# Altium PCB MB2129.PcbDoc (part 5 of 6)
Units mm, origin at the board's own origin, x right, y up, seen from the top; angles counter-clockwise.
Board outline 70 x 133.34 mm, 6 copper layers (Top Layer, Signal Layer 1, Signal Layer 2, Signal Layer 3, Signal Layer 4, Bottom Layer), stack 1.57 mm thick; 377 components, 289 nets, 1482 pads, 1373 vias.
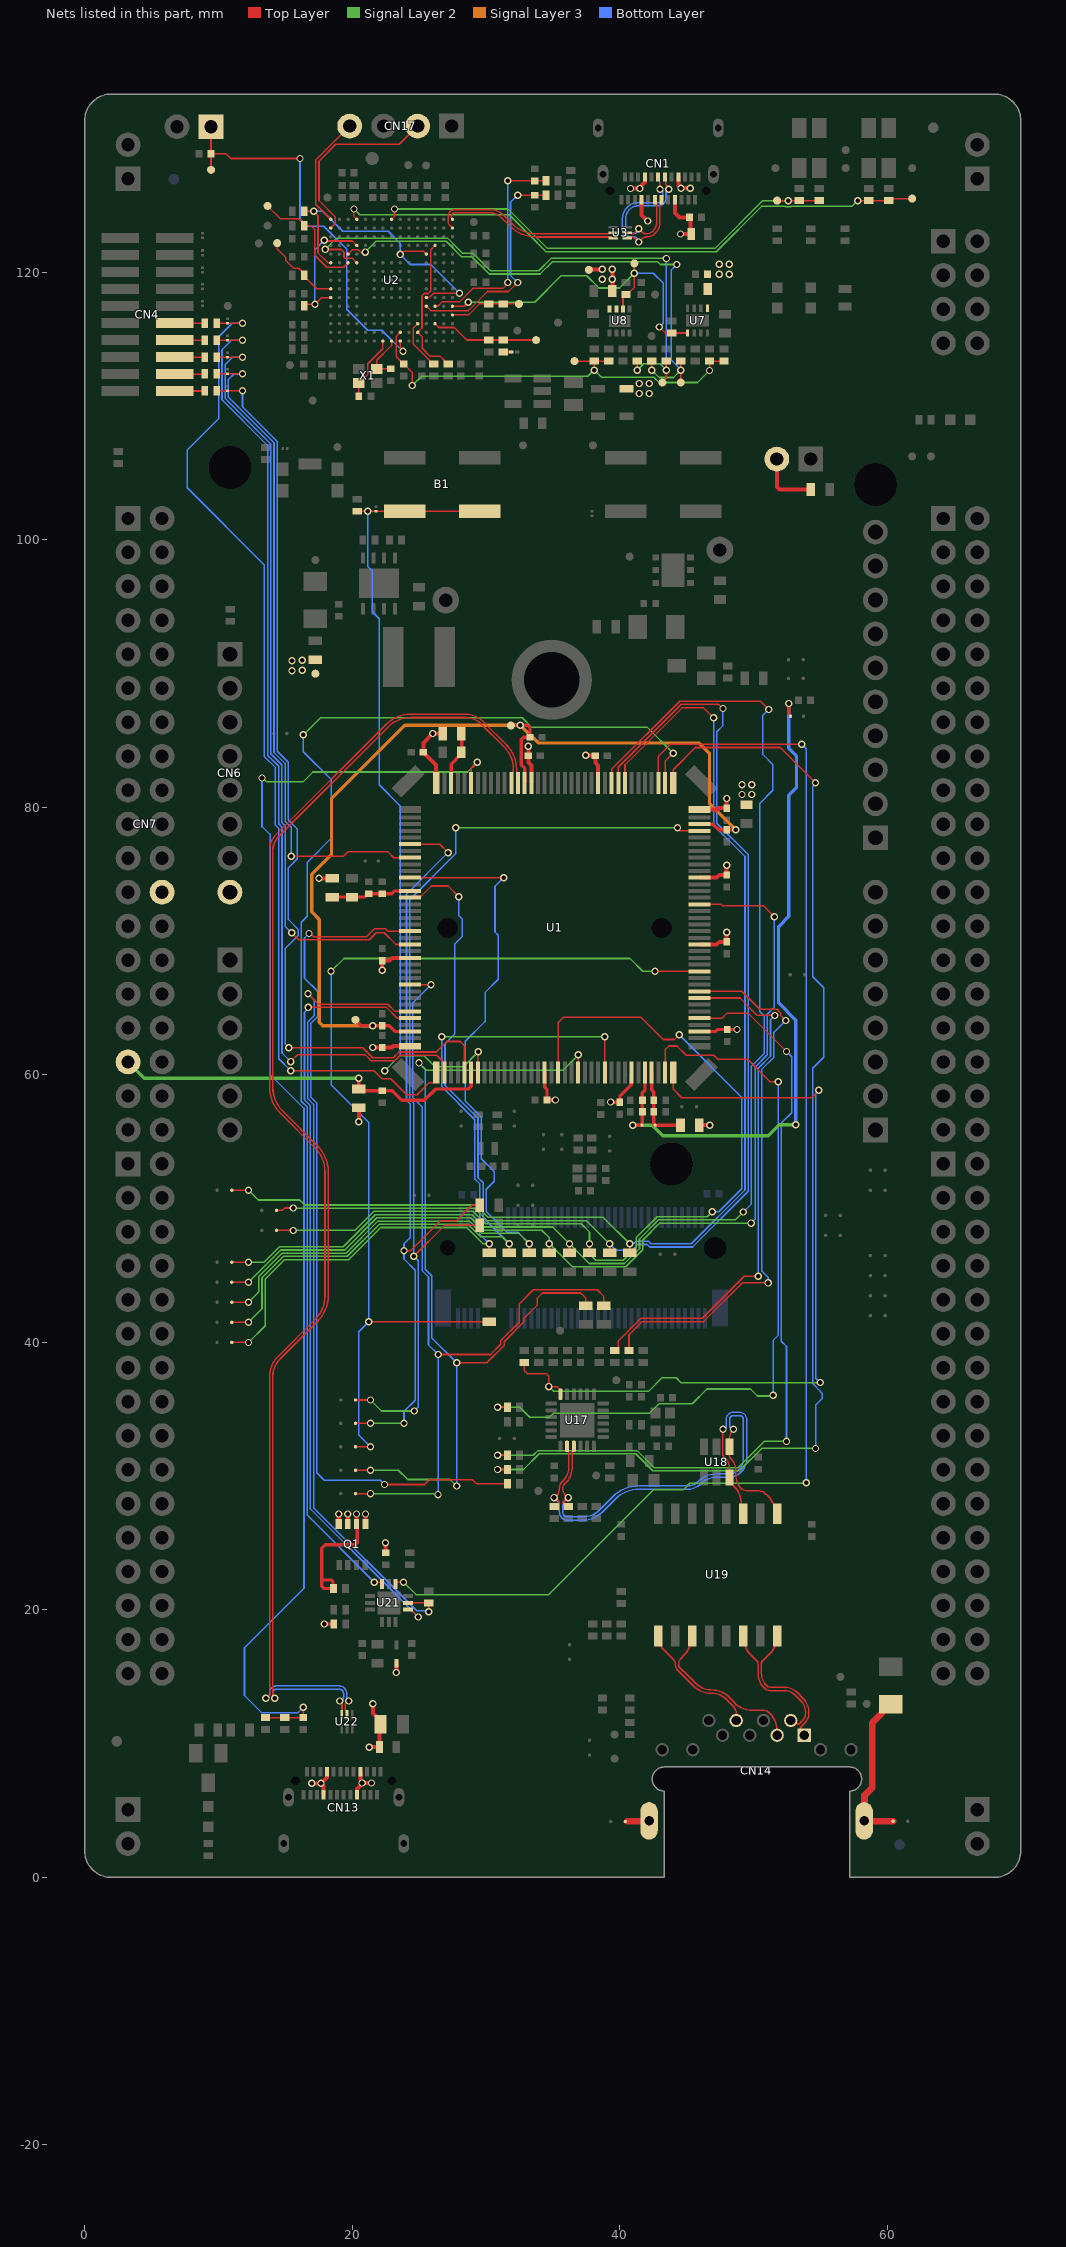
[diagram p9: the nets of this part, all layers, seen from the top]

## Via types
v1: diameter 0.55, hole 0.35, Top Layer to Bottom Layer, tented both sides, 1373 vias

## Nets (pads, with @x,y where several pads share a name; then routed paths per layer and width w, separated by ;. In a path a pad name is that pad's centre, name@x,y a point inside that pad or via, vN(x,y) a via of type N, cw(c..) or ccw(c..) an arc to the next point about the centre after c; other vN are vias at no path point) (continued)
RMII.MDIO: R69.1 U1.36 U17.12 | length 60.4
  Top Layer w0.12: R69.1@32.875,38.5 32.875,37.9 33.104,37.671 34.529,37.671 34.71,37.49 v1(34.71,36.7) 35.304,36.7 35.575,36.429 U17.12@35.575,36.125 ; U1.36@44,60.175 44,58.956 44.651,58.305 46.525,58.305 46.53,58.3 54.35,58.3 v1(54.9,58.85)
  Signal Layer 2 w0.12: v1(34.71,36.7) 35.07,36.34 42.155,36.34 43.165,37.35 44.225,37.35 44.575,37 v1(55,37)
  Bottom Layer w0.12: v1(54.9,58.85) 54.9,58.805 54.67,58.575 54.67,37.33 v1(55,37)
RMII.REF_CLK: R77.1 U1.35 | length 57.8
  Top Layer w0.12: v1(30.875,35.15) R77.1@31.625,35.15 ; U1.35@43.4,60.175 43.4,61.875 43.693,62.168 44.288,62.168 44.976,61.48 47.041,61.48 47.351,61.17 49.58,61.17 51.25,59.5 v1(51.85,59.5)
  Signal Layer 2 w0.12: v1(30.875,35.15) 32.525,35.15 33.275,34.4 34.75,34.4 35.045,34.695 42.222,34.695 42.942,35.415 45.429,35.415 46.534,36.52 49.78,36.52 50.305,35.995 51.42,35.995 v1(51.475,36.05)
  Bottom Layer w0.12: v1(51.475,36.05) 51.475,40.15 51.85,40.525 v1(51.85,59.5)
RMII.RXD0: R74.1 U1.44 | length 39.5
  Top Layer w0.12: R74.1@39.625,39.4 39.705,39.4 39.9,39.595 39.9,40.106 41.594,41.8 46.175,41.8 49.325,44.95 v1(50.375,44.95) ; U1.44@45.975,65.75 49,65.75 50.3,64.45 v1(51.6,64.45)
  Bottom Layer w0.12: v1(50.375,44.95) 50.375,60.502 51.284,61.411 51.284,64.134 v1(51.6,64.45)
RMII.RXD1: R75.1 U1.45 | length 41.2
  Top Layer w0.12: R75.1@40.7,39.4 40.7,40.567 41.693,41.56 46.274,41.56 49.164,44.45 v1(51.1,44.45) ; U1.45@45.975,66.25 49.125,66.25 50.47,64.905 51.412,64.905 51.788,64.905 52.055,64.638 52.055,64.445 v1(52.425,64.075)
  Bottom Layer w0.12: v1@51.1,44.454 51.1,44.868 50.615,45.353 50.615,60.402 51.524,61.311 51.524,63.174 v1(52.425,64.075)
RMII.TX_EN: R80.1 U1.41 | length 61.5
  Top Layer w0.12: v1(30.875,31.575) R80.1@31.625,31.575 ; U1.41@45.975,64.25 47.65,64.25 48.025,64.625 49.6,64.625 v1(52.475,61.75)
  Signal Layer 2 w0.12: v1(30.875,31.575) 33.55,31.575 33.89,31.915 41.3,31.915 42.575,30.64 48.855,30.64 50.815,32.6 v1(52.475,32.6)
  Bottom Layer w0.12: v1(52.475,32.6) 52.475,39.696 52.09,40.081 52.09,56.402 52.87,57.182 52.87,61.355 v1(52.475,61.75)
RMII.TXD0: R82.1 U1.73 | length 90.7
  Top Layer w0.12: v1(30.875,30.5) R82.1@31.625,30.5 ; U1.73@44,81.825 44,82.827 45.658,84.485 52.015,84.485 v1(54.65,81.85)
  Signal Layer 2 w0.12: v1(30.875,30.5) 32.814,30.5 33.989,31.675 41.2,31.675 42.475,30.4 48.955,30.4 50.655,32.1 54.625,32.1 v1(54.65,32.075)
  Bottom Layer w0.12: v1(54.65,32.075) 54.65,35.307 55.155,35.812 55.155,36.188 54.99,36.353 54.99,36.367 54.43,36.927 54.43,60.505 55.255,61.33 55.255,66.527 54.43,67.352 54.43,81.565 54.65,81.785 v1(54.65,81.85)
RMII.TXD1: R83.1 U1.127 | length 64.1
  Top Layer w0.12: v1(16.775,70.575) 16.891,70.575 17.126,70.34 21.068,70.34 21.645,70.917 22.521,70.917 22.688,70.75 U1.127@24.325,70.75 ; v1(22.425,29.375) 25.425,29.375 25.775,29.725 29,29.725 29.3,29.425 R83.1@31.625,29.425
  Bottom Layer w0.12: v1(16.775,70.575) 16.44,70.24 16.44,67.235 17.42,66.255 17.42,64.365 16.92,63.865 16.92,58.336 17.36,57.896 17.36,30.264 17.924,29.7 22.1,29.7 v1(22.425,29.375)
RX_N: CN14.6 U19.9 | length 9.3
  Top Layer w0.1: U19.9@42.88,18.05 ccw(c44.401,18.05) 43.325,16.975 43.998,16.302 cw(c43.571,15.875) 44.175,15.875 ccw(c44.718,15.875) 44.334,15.491 45.502,14.323 ccw(c46.825,15.646) 46.825,13.775 cw(c46.825,12.085) 48.02,13.28 48.475,12.825 cw(c47.896,12.246) 48.715,12.246 CN14.6@48.715,11.73
RX_P: CN14.3 U19.11 | length 12.4
  Top Layer w0.1: U19.11@45.42,18.05 cw(c43.416,18.05) 44.833,16.633 44.6,16.4 ccw(c45.022,15.978) 44.425,15.978 44.425,15.875 ccw(c44.718,15.875) 44.511,15.667 45.077,15.102 45.679,14.5 ccw(c46.825,15.646) 46.825,14.025 cw(c46.825,12.085) 48.193,13.46 48.564,13.089 48.65,13.003 cw(c48.58,12.932) 48.655,12.999 48.727,12.918 ccw(c49.938,14.463) 49.938,12.5 50.682,12.5 cw(c50.682,11.732) 51.225,12.275 cw(c49.897,10.947) 51.775,10.947 CN14.3@51.775,10.63
SHGND: C100.1 CN14.SH1 CN14.SH2 SB43.1 SB44.1 | length 13.4
  Top Layer w0.5: 40.58,4.2 CN14.SH2@42.235,4.2 ; C100.1@60.275,12.95 58.9,11.575 58.9,6.719 58.315,6.134 58.315,4.2 SB43.1@60.45,4.2
STLK_LED: R11.1 R12.2 TP10.1 U2.D15 | length 45.6
  Top Layer w0.12: v1(20.135,124.75) 20.135,124.19 U2.D15@20.35,123.975 ; v1(57.8,125.375) R11.1@58.625,125.375 R12.2@60.125,125.375 60.275,125.525 TP10.1@61.875,125.525
  Signal Layer 2 w0.12: v1(20.135,124.75) 20.57,124.315 31.746,124.315 33.236,122.824 34.501,121.56 47.224,121.56 50.604,124.94 52.392,124.94 52.412,124.92 52.788,124.92 52.808,124.94 57.365,124.94 v1(57.8,125.375)
STLK_NRST: C1.2 JP3.1 TP8.1 U2.J1 | length 29.8
  Top Layer w0.12: JP3.1@9.445,130.9 9.445,128.88 C1.2@9.45,128.875 ; TP8.1@9.45,127.675 C1.2@9.45,128.875 ; v1(16.1,128.525) 10.925,128.525 10.575,128.875 C1.2@9.45,128.875 ; U2.J1@23.6,114.875 23.6,114.385 23.8,114.185 v1(23.8,114.1)
  Bottom Layer w0.12: v1(16.1,128.525) 16.1,124.034 16.671,123.463 17.887,123.463 19.597,121.753 19.597,117.244 21.166,115.675 22.225,115.675 v1(23.8,114.1)
STLK_OSC_IN: C35.2 U2.G1 X1.1 | length 4.9
  Top Layer w0.12: C35.2@20.5,110.75 X1.1@20.5,111.75 20.55,111.75 21.175,112.375 21.175,113.175 22.3,114.3 U2.G1@22.3,114.875
STLK_OSC_OUT: C33.1 U2.H1 X1.3 | length 3.7
  Top Layer w0.12: X1.3@21.6,112.8 21.85,113.05 21.85,113.44 22.95,114.54 U2.H1@22.95,114.875 ; X1.3@21.85,112.8 C33.1@22.875,112.8
STLK_SWCLK: CN17.2 U2.A14 | length 14.1
  Top Layer w0.12: U2.A14@18.4,123.325 18.725,123.65 18.725,124.175 17.525,125.375 17.525,128.321 18.784,129.58 23.525,129.58 CN17.2@24.895,130.95
STLK_SWDIO: CN17.4 U2.A15 | length 8.5
  Top Layer w0.12: U2.A15@18.4,123.975 17.275,125.1 17.275,128.41 CN17.4@19.815,130.95
STLK_UCPD_CC1_C: C10.1 R13.1 U2.M5 | length 16.9
  Top Layer w0.12: U2.M5@25.55,117.475 25.875,117.15 28.7,117.15 30.125,118.575 31.7,118.575 v1(32.375,119.25) ; v1(32.375,125.775) C10.1@33.65,125.775 R13.1@34.5,125.775
  Bottom Layer w0.12: v1(32.375,119.25) 31.845,119.78 31.845,125.245 v1(32.375,125.775)
STLK_UCPD_CC2_C: C2.1 R6.1 U2.N5 | length 16.7
  Top Layer w0.12: U2.N5@26.2,117.475 26.4,117.475 26.725,117.8 28.025,117.8 29.06,118.835 31.312,118.835 31.625,119.148 v1(31.625,119.25) ; v1(31.625,126.85) C2.1@33.65,126.85 R6.1@34.5,126.85
  Bottom Layer w0.12: v1(31.625,119.25) v1(31.625,126.85)
STLK_USB_CN_N: CN1.A7 CN1.B7 U3.2 | length 12.6
  Top Layer w0.12: U3.2@40.575,122.975 40.768,122.975 cw(c40.768,122.838) 40.865,122.935 ccw(c40.962,123.032) 40.962,122.895 ccw(c40.962,123.096) 41.104,122.954 v1(41.425,123.275) 41.685,123.015 ccw(c41.975,123.305) 41.975,122.895 42.005,122.895 ccw(c42.005,123.595) 42.5,123.1 ccw(c41.86,123.74) 42.765,123.74 42.765,125.018 ccw(c42.543,125.018) 42.7,125.175 cw(c42.857,125.332) 42.635,125.332 CN1.A7@42.635,125.44 ; CN1.B7@43.385,127.14 43.46,127.065 43.46,126.566 43.685,126.341 v1(43.685,126.225)
  Bottom Layer w0.12: v1(41.425,123.275) cw(c41.075,123.275) 41.075,122.925 40.75,122.925 cw(c40.75,123.225) 40.45,123.225 40.45,124.025 cw(c41.41,124.025) 41.41,124.985 42.88,124.985 ccw(c42.88,125.575) 43.47,125.575 43.47,126.01 cw(c43.685,126.01) v1(43.685,126.225)
STLK_USB_CN_P: CN1.A6 CN1.B6 U3.1 | length 13.3
  Top Layer w0.12: U3.1@40.575,122.575 40.768,122.575 ccw(c40.768,122.712) 40.865,122.615 cw(c40.962,122.518) 40.962,122.655 cw(c40.962,122.454) 41.104,122.596 v1(41.425,122.275) 41.685,122.535 cw(c41.975,122.245) 41.975,122.655 42.005,122.655 ccw(c42.005,123.595) 42.67,122.93 ccw(c41.86,123.74) 43.005,123.74 43.005,125.018 cw(c43.227,125.018) 43.07,125.175 ccw(c42.913,125.332) 43.135,125.332 CN1.A6@43.135,125.44 ; CN1.B6@42.885,127.14 42.975,127.05 42.975,126.81 43.015,126.77 v1(43.015,126.225)
  Bottom Layer w0.12: v1(41.425,122.275) ccw(c41.015,122.275) 41.015,122.685 40.75,122.685 cw(c40.75,123.225) 40.21,123.225 40.21,124.025 cw(c41.41,124.025) 41.41,125.225 42.88,125.225 ccw(c42.88,125.575) 43.23,125.575 43.23,126.01 ccw(c43.015,126.01) v1(43.015,126.225)
STLK_USB_N: U2.R14 U3.5 | length 14.2
  Top Layer w0.12: U2.R14@27.5,123.325 27.334,123.491 cw(c27.718,123.875) 27.175,123.875 27.175,124.188 cw(c27.687,124.188) 27.325,124.55 cw(c27.687,124.188) 27.687,124.7 30.306,124.7 cw(c30.306,123.231) 31.345,124.27 31.975,123.639 ccw(c33.772,125.435) 33.772,122.895 39.138,122.895 ccw(c39.138,123.032) 39.235,122.935 cw(c39.332,122.838) 39.332,122.975 U3.5@39.525,122.975
STLK_USB_P: U2.R15 U3.6 | length 13.1
  Top Layer w0.12: U2.R15@27.5,123.975 cw(c27.741,124.216) 27.423,124.094 cw(c27.535,124.136) 27.415,124.136 27.415,124.188 cw(c27.687,124.188) 27.427,124.267 cw(c27.687,124.188) 27.495,124.38 cw(c27.687,124.188) 27.687,124.46 30.306,124.46 cw(c30.306,123.231) 31.175,124.1 31.806,123.469 ccw(c33.772,125.435) 33.772,122.655 39.138,122.655 cw(c39.138,122.518) 39.235,122.615 ccw(c39.332,122.712) 39.332,122.575 U3.6@39.525,122.575
STLK_VCP_RX: R16.1 TP12.1 U2.C10 | length 9.2
  Top Layer w0.12: TP12.1@13.675,124.975 14.64,124.01 16.006,124.01 16.421,123.595 R16.1@16.421,123.5 16.925,123.5 17.21,123.215 17.21,121.29 18.1,120.4 19.375,120.4 U2.C10@19.7,120.725
STLK_VCP_TX: R20.1 TP16.1 U2.A7 | length 5.9
  Top Layer w0.12: TP16.1@14.4,122.2 14.4,121.758 15.05,121.108 15.05,120.875 15.615,120.31 16.01,120.31 16.425,119.895 16.425,119.705 17.355,118.775 U2.A7@18.4,118.775
T_JTDI: R44.1 U2.L3 | length 3.8
  Top Layer w0.12: U2.L3@24.9,116.175 24.575,115.85 24.575,114.65 25.81,113.415 25.81,113.345 26.005,113.15 R44.1@26.1,113.15
T_PWR_EN: R21.2 R25.2 TP21.1 U2.R5 U7.5 U8.2 | length 27.4
  Top Layer w0.12: U2.R5@27.5,117.475 28.375,117.475 v1(28.675,117.775) ; U8.2@40.25,117.275 40.25,118.155 40.445,118.35 R21.2@40.475,118.35 40.57,118.35 41.1,118.88 v1(41.1,119.95) TP21.1@41.1,120.675 ; v1(42.975,115.925) 43.425,115.475 R25.2@43.9,115.475 U7.5@45.075,115.475
  Signal Layer 2 w0.12: v1(28.675,117.775) 33.65,117.775 35.625,119.75 37.549,119.75 38.458,118.841 39.991,118.841 v1(41.1,119.95)
  Bottom Layer w0.12: v1(41.1,119.95) 42.525,119.95 43.26,119.215 43.26,116.21 v1(42.975,115.925)
T_PWR_EXT: R23.1 R24.1 TP24.1 U2.R4 | length 5.3
  Top Layer w0.12: U2.R4@27.5,116.825 28.7,116.825 29.525,117.65 R23.1@30.225,117.65 R24.1@31.3,117.65 TP24.1@32.475,117.65
T_PWR_INT: C28.1 R33.2 R40.2 R41.2 R42.2 TP30.1 U2.J2 | length 33.1
  Top Layer w0.12: U2.J2@23.6,115.525 23.29,115.215 23.29,113.71 23.63,113.37 23.63,113.345 23.825,113.15 C28.1@23.85,113.15 23.875,113.15 24.5,112.525 v1(24.5,111.55) ; TP30.1@36.625,113.375 R33.2@38.1,113.375 ; v1(38.1,112.7) R33.2@38.1,113.375 ; R42.2@39.175,113.375 R33.2@38.1,113.375 ; v1(46.725,112.675) R40.2@46.725,113.375 R41.2@47.8,113.375
  Signal Layer 2 w0.12: v1(24.5,111.55) 25.2,112.25 37.625,112.25 38.1,112.725 38.65,112.175 42.55,112.175 42.95,111.775 45.825,111.775 v1(46.725,112.675)
T_PWR_LED: R9.2 R10.2 TP11.1 U2.H15 | length 36.2
  Top Layer w0.12: U2.H15@22.95,123.975 23.165,124.19 v1(23.165,124.75) ; TP11.1@51.775,125.375 v1(52.6,125.375) R9.2@53.425,125.375 R10.2@54.925,125.375
  Signal Layer 2 w0.12: v1(23.165,124.75) 31.65,124.75 34.6,121.8 47.125,121.8 50.7,125.375 v1(52.6,125.375)
T_PWR_SEL1: R35.2 R37.2 TP32.1 U2.D10 | length 43.8
  Top Layer w0.12: v1(17.98,121.725) 17.985,121.72 19.18,121.72 19.395,121.505 19.395,121.13 19.475,121.05 20.025,121.05 U2.D10@20.35,120.725 ; v1(41.325,112.7) R35.2@41.325,113.375 ; TP32.1@42.95,111.775 TP32.1@43.075,111.9 ; TP32.1@43.2,111.775 43.49,112.065 43.49,112.69 v1(43.5,112.7) R37.2@43.5,113.375
  Signal Layer 2 w0.12: v1(17.98,121.725) 18.828,122.573 27.127,122.573 28.275,121.425 29.05,121.425 30.35,120.125 33.95,120.125 34.875,121.05 v1(43.5,121.05) ; v1(41.325,112.7) 41.805,113.18 43.02,113.18 v1(43.5,112.7)
  Bottom Layer w0.12: v1(43.5,112.7) v1(43.5,121.05)
T_PWR_SEL2: R36.2 R38.2 TP33.1 U2.C11 | length 39.9
  Top Layer w0.12: U2.C11@19.7,121.375 20.025,121.7 20.456,121.7 20.631,121.525 v1(20.975,121.525) ; v1(42.4,112.7) R36.2@42.4,113.375 ; TP33.1@44.575,111.775 v1(44.575,112.7) R38.2@44.575,113.375
  Signal Layer 2 w0.12: v1(20.975,121.525) 21.783,122.333 27.028,122.333 28.176,121.185 28.951,121.185 30.251,119.885 34.049,119.885 34.974,120.81 42.84,120.81 43.055,120.595 44.27,120.595 v1(44.275,120.6) ; v1(42.4,112.7) 42.95,112.15 44.025,112.15 v1(44.575,112.7)
  Bottom Layer w0.12: v1(44.275,120.6) 43.85,120.175 43.85,113.468 44.575,112.743 v1(44.575,112.7)
T_SWCLK: R15.1 U2.A10 U2.M6 U2.M11 | length 23.9
  Top Layer w0.12: R15.1@16.421,124.575 v1@17.141,124.575 ; v1(17.141,124.57) 17.141,124.545 17.45,124.236 17.45,121.463 18.188,120.725 U2.A10@18.4,120.725 ; v1(23.6,121.35) 23.635,121.35 23.885,121.6 25.325,121.6 U2.M11@25.55,121.375 ; U2.M6@25.55,118.125 25.769,118.125 26.094,118.45 v1(28.025,118.45)
  Bottom Layer w0.12: v1(17.141,124.57) 17.805,124.57 19.3,123.075 22.7,123.075 23.6,122.175 v1(23.6,121.35) 24.35,120.6 25.875,120.6 v1(28.025,118.45)
T_SWDIO: R45.1 U2.L2 U2.N12 | length 11
  Top Layer w0.12: U2.N12@26.2,122.025 25.875,121.7 25.875,118.625 25.68,118.43 25.386,118.43 25.225,118.269 25.225,115.85 U2.L2@24.9,115.525 25.245,115.18 25.245,114.326 25.846,113.725 26.6,113.725 26.885,113.44 26.885,113.345 27.08,113.15 R45.1@27.175,113.15
T_SWO: R22.1 U2.A6 U2.D12 | length 9.9
  Top Layer w0.12: R22.1@16.425,117.525 16.53,117.63 v1(17.22,117.63) ; v1@17.225,117.625 17.725,118.125 U2.A6@18.4,118.125 ; v1(17.925,122.4) 17.97,122.355 18.529,122.355 20.02,122.355 U2.D12@20.35,122.025
  Bottom Layer w0.12: v1(17.22,117.63) 17.22,121.695 v1(17.925,122.4)
T_VCC: LNK1.2 R31.2 | length 0.6
  Top Layer w0.2: R31.2@31.3,114.05 LNK1.2@31.9,114.05
T_VCC_AIN: R30.1 R31.1 TP29.1 U2.N3 | length 8.1
  Top Layer w0.12: U2.N3@26.2,116.175 26.485,115.89 27.637,115.89 28.577,114.95 R30.1@30.225,114.95 R31.1@31.3,114.95 TP29.1@33.75,114.95
TD_N: R84.1 U17.20 U18.3 U19.3 | length 35.5
  Top Layer w0.1: R84.1@35.1,27.725 35.257,27.882 cw(c35.373,27.765) 35.373,27.93 35.4,27.93 ccw(c35.4,28.03) 35.471,27.959 ccw(c35.4,28.03) 35.5,28.03 ccw(c35.4,28.03) 35.471,28.101 35.222,28.349 ccw(c35.1,28.228) v1(35.1,28.4) ccw(c35.1,28.578) 35.226,28.452 ccw(c34.565,29.113) 35.5,29.113 cw(c36.161,29.113) 35.694,29.581 35.79,29.677 ccw(c34.799,30.668) 36.2,30.668 36.2,30.705 ; U17.20@36.075,32.225 36.075,32.025 ccw(c36.288,32.025) 36.137,31.874 cw(c35.987,31.723) 36.2,31.723 36.2,30.705 ; 36.2,30.601 36.2,30.705 ; v1@47.724,33.516 47.724,31.651 ccw(c48.22,31.651) 47.768,31.447 47.994,31.222 cw(c47.495,30.723) 48.2,30.723 U18.3@48.2,29.9 ccw(c48.924,29.9) 48.412,29.388 48.62,29.18 cw(c47.509,28.069) 49.08,28.069 U19.3@49.08,27.2
  Bottom Layer w0.1: v1(35.1,28.4) 35.306,28.194 cw(c34.836,27.725) 35.5,27.725 35.5,27.325 ccw(c36.125,27.325) 36.125,26.7 37.2,26.7 ccw(c37.2,28.821) 38.7,27.321 39.66,28.281 cw(c41.456,26.485) 41.456,29.025 45.136,29.025 ccw(c45.136,30.214) 45.977,29.373 45.983,29.38 cw(c47.3,28.063) 47.3,29.925 48.14,29.925 ccw(c48.14,31.285) 49.102,30.323 ccw(c48.14,31.285) 49.5,31.285 49.5,34.25 ccw(c48.975,34.25) 48.975,34.775 48.475,34.775 ccw(c48.475,34.273) 47.973,34.273 47.973,33.748 cw(c47.725,33.748) v1(47.725,33.5)
TD_P: R85.1 U17.21 U18.4 U19.1 | length 35.5
  Top Layer w0.1: R85.1@36.15,27.725 35.993,27.882 ccw(c35.877,27.765) 35.877,27.93 35.85,27.93 cw(c35.85,28.03) 35.779,27.959 cw(c35.85,28.03) 35.75,28.03 cw(c35.85,28.03) 35.779,28.101 36.028,28.349 cw(c36.15,28.228) v1(36.15,28.4) cw(c36.15,28.578) 36.024,28.452 cw(c36.685,29.113) 35.75,29.113 cw(c36.161,29.113) 35.87,29.404 36.013,29.547 ccw(c34.959,30.601) 36.45,30.601 36.45,31.723 cw(c36.663,31.723) 36.512,31.874 ccw(c36.362,32.025) 36.575,32.025 U17.21@36.575,32.225 ; v1@48.525,33.5 ccw(c49.31,32.715) 48.2,32.715 U18.4@48.2,32.2 48.2,31.562 ccw(c48.528,31.562) 48.296,31.33 48.328,31.298 cw(c47.43,30.4) 48.7,30.4 48.7,30.012 ccw(c49.971,30.012) 49.072,29.114 ccw(c49.588,29.63) 49.588,28.9 50.425,28.9 cw(c50.425,28.236) 50.894,28.706 51.068,28.532 cw(c49.737,27.2) U19.1@51.62,27.2
  Bottom Layer w0.1: v1(36.15,28.4) 35.944,28.194 ccw(c36.414,27.725) 35.75,27.725 35.75,27.325 ccw(c36.125,27.325) 36.125,26.95 37.2,26.95 ccw(c37.2,28.821) 38.523,27.498 39.483,28.458 cw(c41.456,26.485) 41.456,29.275 45.136,29.275 ccw(c45.136,30.214) 45.8,29.55 45.806,29.556 cw(c47.3,28.063) 47.3,30.175 48.14,30.175 ccw(c48.14,31.285) 48.925,30.5 ccw(c48.14,31.285) 49.25,31.285 49.25,34.25 ccw(c48.975,34.25) 48.975,34.525 48.475,34.525 ccw(c48.475,34.273) 48.223,34.273 48.223,33.802 ccw(c48.52,33.802) v1(48.52,33.505)
TRACE.CLK: R26.2 U1.1 U9.1 | length 75.8
  Top Layer w0.12: R26.2@9.875,116.2 9.881,116.206 U9.1@10.7,116.206 v1(11.8,116.206) ; v1(15.4,60.325) 21.626,60.325 22.226,59.725 22.882,59.725 24.082,58.525 24.868,58.525 25.753,59.41 26.11,59.41 26.3,59.6 U1.1@26.3,60.175
  Bottom Layer w0.12: v1(11.8,116.206) 11.031,116.206 10.03,115.205 10.03,109.08 7.675,106.725 7.675,103.9 13.44,98.135 13.44,83.813 14.265,82.988 14.265,78.677 14.515,78.427 14.515,61.21 v1(15.4,60.325)
TRACE.D0: R29.2 U1.2 U25.1 | length 72.2
  Top Layer w0.12: R29.2@9.875,114.925 9.881,114.931 U25.1@10.7,114.931 v1(11.8,114.931) ; v1(15.4,61) 15.925,61.525 20.965,61.525 21.44,61.05 23.178,61.05 23.608,61.48 26.325,61.48 26.81,60.995 26.81,60.265 U1.2@26.9,60.175
  Bottom Layer w0.12: v1(11.8,114.931) 10.978,114.931 10.27,114.223 10.27,110.48 13.68,107.07 13.68,83.912 14.505,83.087 14.505,78.777 14.755,78.527 14.755,61.645 v1(15.4,61)
TRACE.D1: R43.2 U1.129 U26.1 | length 57.6
  Top Layer w0.12: R43.2@9.875,113.65 9.881,113.656 U26.1@10.7,113.656 v1(11.8,113.656) ; v1(15.475,70.625) 16,70.1 21.275,70.1 21.8,70.625 22.4,70.625 23.275,69.75 U1.129@24.325,69.75
  Bottom Layer w0.12: v1(11.8,113.656) 11.053,113.656 10.51,113.113 10.51,110.579 13.92,107.169 13.92,84.012 14.745,83.187 14.745,78.876 14.995,78.626 14.995,71.105 v1(15.475,70.625)
TRACE.D2: R46.2 U1.116 U27.1 | length 49.9
  Top Layer w0.12: R46.2@9.875,112.425 9.881,112.431 U27.1@10.7,112.431 v1(11.8,112.431) ; v1(15.45,76.35) 19.35,76.35 19.675,76.675 22.687,76.675 23.112,76.25 U1.116@24.325,76.25
  Bottom Layer w0.12: v1(11.8,112.431) 11.769,112.4 11.15,112.4 10.75,112 10.75,110.679 14.16,107.269 14.16,84.111 14.985,83.286 14.985,78.976 15.45,78.511 v1(15.45,76.35)
TRACE.D3: R47.2 U1.5 U28.1 | length 69.9
  Top Layer w0.12: R47.2@9.875,111.15 9.881,111.156 U28.1@10.7,111.156 v1(11.8,111.156) ; v1(15.25,62.025) 20.804,62.025 21.539,61.29 23.078,61.29 23.508,61.72 26.295,61.72 27.075,62.5 28.075,62.5 28.4,62.175 U1.5@28.4,60.175
  Bottom Layer w0.12: v1(11.8,111.156) 11.8,109.968 14.4,107.368 14.4,84.211 15.225,83.386 15.225,79.075 15.905,78.395 15.905,76.162 15.235,75.492 15.235,71.615 15.96,70.89 15.96,70.412 14.995,69.447 14.995,62.31 15.25,62.055 v1(15.25,62.025)
TRACECLK: CN4.12 R26.1 | length 2.2
  Top Layer w0.12: CN4.12@6.735,116.215 6.75,116.2 R26.1@8.975,116.2
TRACED0: CN4.14 R29.1 | length 2.2
  Top Layer w0.12: CN4.14@6.735,114.945 8.955,114.945 R29.1@8.975,114.925
TRACED1: CN4.16 R43.1 | length 2.3
  Top Layer w0.12: CN4.16@6.735,113.675 8.95,113.675 R43.1@8.975,113.65
TRACED2: CN4.18 R46.1 | length 2.2
  Top Layer w0.12: CN4.18@6.735,112.405 8.955,112.405 R46.1@8.975,112.425
TRACED3: CN4.20 R47.1 | length 2.2
  Top Layer w0.12: CN4.20@6.735,111.135 8.96,111.135 R47.1@8.975,111.15
TX_N: CN14.2 U19.14 | length 10.1
  Top Layer w0.1: U19.14@49.23,18.05 ccw(c51.234,18.05) 49.817,16.633 50.244,16.206 cw(c49.988,15.95) 50.35,15.95 50.35,15.255 ccw(c51.88,15.255) 50.798,14.173 ccw(c51.277,14.652) 51.277,13.975 52.325,13.975 cw(c52.325,12.889) 53.093,13.657 53.564,13.186 cw(c52.753,12.375) 53.9,12.375 53.9,12.254 cw(c53.171,12.254) 53.687,11.738 53.64,11.692 cw(c53.611,11.72) 53.611,11.68 53.416,11.484 cw(c53.345,11.555) 53.345,11.455 cw(c53.345,11.555) 53.274,11.484 53.166,11.592 ccw(c52.834,11.26) 52.834,11.73 CN14.2@52.795,11.73
TX_P: CN14.1 U19.16 | length 10.5
  Top Layer w0.1: U19.16@51.77,18.05 cw(c49.887,18.05) 51.218,16.718 50.706,16.206 ccw(c50.962,15.95) 50.6,15.95 50.6,15.255 ccw(c51.88,15.255) 50.975,14.35 ccw(c51.277,14.652) 51.277,14.225 52.325,14.225 cw(c52.325,12.889) 53.27,13.834 53.741,13.363 cw(c52.753,12.375) 54.15,12.375 54.15,12.254 cw(c53.171,12.254) 53.864,11.562 53.743,11.442 cw(c53.715,11.47) 53.715,11.43 53.607,11.321 ccw(c53.848,11.08) 53.507,11.08 ccw(c53.848,11.08) 53.607,10.838 CN14.1@53.815,10.63
UCPD.CC1: U1.74 U21.3 | length 99.8
  Top Layer w0.12: v1(21.655,22.075) 22.16,22.075 22.25,21.985 U21.3@22.25,21.95 ; U1.74@43.4,81.825 43.4,83.45 v1(44,84.05)
  Signal Layer 2 w0.12: v1(16.35,85.425) 17.635,86.71 32.71,86.71 33.41,86.01 42.04,86.01 v1(44,84.05)
  Bottom Layer w0.12: v1(16.35,85.425) 16.35,84.175 18.425,82.1 18.425,77.675 16.64,75.89 16.64,71.865 16.2,71.425 16.2,58.038 16.64,57.598 16.64,27.09 v1(21.655,22.075)
UCPD.CC2: U1.75 U21.1 | length 103.1
  Top Layer w0.12: U21.1@23.25,21.95 23.25,21.985 23.34,22.075 v1(23.845,22.075) ; U1.75@42.9,81.825 42.9,83.825 43.8,84.725 v1(53.625,84.725)
  Signal Layer 2 w0.12: v1(23.845,22.075) 24.77,21.15 34.7,21.15 42.525,28.975 44.75,28.975 45.25,29.475 53.925,29.475 v1(53.95,29.5)
  Bottom Layer w0.12: v1(53.625,84.725) 53.95,84.4 v1(53.95,29.5)
UCPD.DBN: U1.140 U21.10 | length 58.2
  Top Layer w0.12: v1(16.725,65.05) 22.565,65.05 23.365,64.25 U1.140@24.325,64.25 ; U21.10@24.175,20.025 24.4,20.025 v1(24.95,19.475)
  Bottom Layer w0.12: v1(16.725,65.05) 16.725,64.977 16.44,64.692 16.44,58.137 16.88,57.697 16.88,27.545 21.8,22.625 v1(24.95,19.475)
UCPD.FLT: R88.2 U1.139 U21.11 | length 61.2
  Top Layer w0.12: v1(16.7,66.075) 17.485,65.29 22.664,65.29 23.204,64.75 U1.139@24.325,64.75 ; U21.11@24.175,20.525 R88.2@25.725,20.525 v1(25.725,19.875)
  Bottom Layer w0.12: v1(16.7,66.075) 17.18,65.595 17.18,64.465 16.68,63.965 16.68,58.236 17.12,57.796 17.12,27.644 24.834,19.93 25.67,19.93 v1(25.725,19.875)
UCPD.VBUS_SENSE: C105.2 R100.1 R101.2 U1.103 | length 99
  Top Layer w0.12: R100.1@13.525,11.95 R101.2@14.95,11.95 C105.2@16.35,11.95 v1(16.35,12.725) ; U1.103@28.9,81.825 28.9,82.926 v1(29.349,83.375)
  Signal Layer 2 w0.12: v1(13.265,82.201) 13.324,82.201 13.616,81.909 16.331,81.909 17.072,82.65 28.624,82.65 v1(29.349,83.375)
  Bottom Layer w0.12: v1(13.265,82.201) 13.265,78.578 13.865,77.978 13.865,60.033 16.4,57.498 16.4,21.625 11.95,17.175 11.95,13.6 13.225,12.325 15.95,12.325 v1(16.35,12.725)
USB_HS_N: U1.96 U22.5 | length 101.4
  Top Layer w0.12: v1(13.555,13.4) ccw(c13.555,13.675) 13.777,13.513 ccw(c13.68,13.583) 13.794,13.546 13.824,13.638 ccw(c13.71,13.675) 13.83,13.675 13.83,37.441 cw(c15.951,37.441) 14.451,38.941 17.231,41.72 ccw(c15.435,43.517) 17.975,43.517 17.975,52.748 ccw(c15.435,52.748) 17.231,54.544 14.644,57.131 cw(c16.61,59.097) 13.83,59.097 13.83,76.763 cw(c15.608,76.763) 14.351,78.021 22.521,86.191 cw(c24.402,84.31) 24.402,86.97 28.493,86.97 cw(c28.493,85.143) 29.785,86.435 31.535,84.685 cw(c29.7,82.85) 32.295,82.85 32.295,82.66 cw(c32.259,82.624) 32.31,82.624 32.31,82.042 ccw(c32.617,82.042) U1.96@32.4,81.825 ; U22.5@19.62,12.16 19.58,12.417 cw(c19.62,12.53) 19.5,12.53 19.5,12.94 cw(c19.755,12.94) v1(19.755,13.195)
  Bottom Layer w0.12: v1(13.555,13.4) ccw(c13.555,13.675) 13.777,13.513 ccw(c13.68,13.583) 13.794,13.546 13.824,13.638 ccw(c13.71,13.675) 13.83,13.675 13.83,13.807 cw(c14.343,13.807) 14.343,14.32 19,14.32 cw(c19,13.72) 19.6,13.72 19.6,13.47 ccw(c19.72,13.47) 19.619,13.405 v1(19.755,13.195)
USB_HS_P: U1.97 U22.6 | length 99.7
  Top Layer w0.12: v1(14.225,13.4) 14.089,13.61 cw(c14.19,13.675) 14.07,13.675 14.07,37.441 cw(c15.951,37.441) 14.621,38.771 17.401,41.551 ccw(c15.435,43.517) 18.215,43.517 18.215,52.748 ccw(c15.435,52.748) 17.401,54.714 14.814,57.3 cw(c16.61,59.097) 14.07,59.097 14.07,76.734 cw(c16.089,76.734) 14.083,76.964 cw(c15.608,76.763) 14.521,77.851 22.691,86.022 ; v1(19.085,13.195) 19.221,12.985 cw(c19.12,12.92) 19.24,12.92 19.24,12.18 cw(c19.22,12.18) U22.6@19.22,12.16 ; 22.691,86.022 cw(c24.402,84.31) 24.402,86.73 28.493,86.73 cw(c28.493,85.143) 29.615,86.265 31.364,84.516 cw(c29.7,82.85) 32.055,82.85 32.055,82.765 cw(c31.79,82.765) 31.977,82.578 ccw(c32.165,82.39) 31.9,82.39 U1.97@31.9,81.825
  Bottom Layer w0.12: v1(14.225,13.4) 14.089,13.61 cw(c14.19,13.675) 14.07,13.675 14.07,13.807 cw(c14.343,13.807) 14.343,14.08 19,14.08 cw(c19,13.72) 19.36,13.72 19.36,13.47 cw(c19.24,13.47) 19.354,13.433 19.324,13.341 cw(c19.21,13.378) 19.307,13.308 cw(c19.085,13.47) v1(19.085,13.195)
USER: B1.1 B1.2 R110.2 U1.7 U13.1 | length 62.3
  Top Layer w0.12: R110.2@20.375,102.15 v1(21.175,102.15) ; v1@21.181,102.156 B1.2@23.944,102.156 ; B1.2@23.95,102.15 B1.1@29.55,102.15 ; U1.7@29.4,60.175 29.4,61.7 v1(29.434,61.734)
  Signal Layer 2 w0.12: v1(22.45,60.325) 23.55,61.425 25.4,61.425 26.225,60.6 28.3,60.6 v1(29.434,61.734)
  Bottom Layer w0.12: v1(21.175,102.15) 21.175,98.019 21.5,97.694 21.5,94.625 22.025,94.1 22.025,81.689 23.585,80.129 23.585,61.46 v1(22.45,60.325)
VBAT: C68.2 CN7.33 R65.2 U1.6 | length 28.6
  Top Layer w0.25: R65.2@20.5,59 v1(20.5,59.75) ; R65.2@20.6,58.825 C68.2@22.25,58.825 23,58.825 23.726,58.099 25.399,58.099 26.25,58.95 28.7,58.95 28.9,59.15 U1.6@28.9,60.175 28.9,60.2 U1.6@28.925,60.225
  Signal Layer 2 w0.25: CN7.33@3.246,60.97 4.466,59.75 v1(20.5,59.75)
VBUS_STLK: C11.1 C17.2 C20.2 C21.2 CN1.A4 CN1.A9 CN1.B4 CN1.B9 D1.1 TP22.1 U4.1 U7.1 U8.3 U8.4 | length 12.2
  Top Layer w0.3: TP22.1@37.7,120.2 37.725,120.225 38.675,120.225 v1(38.7,120.25) ; C21.2@39.45,118.625 v1(39.45,119.5) v1@39.45,120.375 ; v1(40.81,126.275) v1(41.51,126.275) 41.558,126.323 41.558,126.431 41.885,126.758 CN1.B4@41.885,127.14 ; CN1.A9@41.635,125.44 41.635,124.315 v1(42.1,123.85) ; CN1.A4@44.135,125.44 44.135,124.465 44.475,124.125 C11.1@45.225,124.125 45.287,124.063 45.287,122.938 U4.1@45.35,122.875 v1(44.55,122.875) ; CN1.B9@44.385,127.14 44.385,126.5 v1(44.585,126.3) v1(45.285,126.3)
  other v1: 41.475,110.95 42.225,110.95 41.475,111.7 42.225,111.7 38.7,119.5 47.45,119.875 48.2,119.875 39.45,120.25 47.45,120.625 48.2,120.625
VBUSc: C96.2 C104.1 CN13.A4 CN13.A9 CN13.B4 CN13.B9 D3.1 Q1.5 Q1.6 Q1.7 Q1.8 R91.2 R97.2 U23.1 | length 24.2
  Top Layer w0.25: v1(17.925,18.95) R91.2@18.625,18.95 ; Q1.6@20.325,26.425 20.375,26.375 20.375,25.021 20.229,24.875 17.975,24.875 17.725,24.625 17.725,22.241 ; 17.725,22.241 17.725,21.775 17.9,21.6 R97.2@18.6,21.6 18.575,21.625 18.575,22.094 18.429,22.241 17.725,22.241
  Top Layer w0.3: v1(16.97,7.035) v1(17.67,7.035) ; CN13.B9@17.87,6.195 17.87,6.835 v1(17.67,7.035) ; CN13.A4@18.12,7.895 18.12,7.485 v1(17.67,7.035) ; Q1.8@19,26.425 v1(19,27.175) ; Q1.7@19.675,26.425 v1(19.675,27.175) ; Q1.6@20.325,26.425 v1(20.325,27.175) ; CN13.B4@20.37,6.195 20.37,6.617 20.745,6.992 v1(20.745,7.06) ; CN13.A9@20.62,7.895 20.62,7.253 20.745,7.128 v1(20.745,7.06) ; Q1.5@21,26.425 v1(21,27.175) ; v1(21.27,9.735) U23.1@22.045,9.735 22.045,11.385 C104.1@22.12,11.46 22.12,11.71 21.555,12.275 v1(21.555,12.991) ; v1(21.445,7.06) v1(20.745,7.06) ; C96.2@22.5,24.275 v1(22.5,25.025) ; v1@23.3,15.3 D3.1@23.3,16.025
  other v1: 23.3,15.325
VCAP: C54.1 C61.1 C64.1 TP52.1 TP53.1 U1.70 U1.95 U1.142 | length 73.1
  Top Layer w0.25: TP53.1@20.25,64.125 20.7,63.675 v1(21.55,63.675) C64.1@22.25,63.675 22.775,63.675 23.2,63.25 U1.142@24.325,63.25 ; TP52.1@31.9,86.15 v1(32.575,86.15) 33.1,86.15 33.3,85.95 C54.1@33.3,85.25 ; U1.95@32.9,81.825 32.9,82.95 32.65,83.2 32.65,85.075 32.816,85.241 C54.1@33.266,85.241 ; U1.70@45.975,78.75 45.978,78.747 46.978,78.747 47.4,78.325 C61.1@48,78.325 v1(48.675,78.325)
  Signal Layer 3 w0.25: v1(21.55,63.675) 17.8,63.675 17.55,63.925 17.55,71.623 16.975,72.198 16.975,74.992 18.455,76.472 18.455,80.654 23.951,86.15 v1(32.575,86.15) 33.9,84.825 45.908,84.825 46.725,84.008 46.725,80.275 v1(48.675,78.325)
VDD_MCU: C48.2 C51.2 C52.2 C53.2 C57.2 C60.2 C65.2 C66.2 C67.2 C71.2 C72.2 C74.2 JP5.2 R62.1 R64.1 R65.1 R68.1 R99.2 U1.17 U1.30 U1.39 U1.52 U1.62 U1.72 U1.84 U1.94 U1.108 U1.131 U1.144 | length 41.6
  Top Layer w0.25: U1.17@34.4,60.175 34.4,59.075 34.575,58.9 C72.2@34.575,58.125 ; U1.84@38.375,81.85 U1.84@38.4,81.825 ; v1(39.325,57.975) 39.337,57.963 C74.2@40.013,57.963 ; C74.2@40,57.95 40.034,57.984 40.034,58.434 40.875,59.275 40.875,60.15 U1.30@40.9,60.175 ; U1.39@45.975,63.25 47.2,63.25 47.35,63.4 C66.2@48.05,63.4 v1@48.725,63.4
  Top Layer w0.3: v1@17.525,74.75 v1@17.55,74.725 ; v1@17.55,74.7 R62.1@18.475,74.7 ; R62.1@18.475,74.725 R62.1@18.5,74.7 ; v1(20.5,56.5) R65.1@20.5,57.55 ; v1(21.55,62.05) 22.975,62.05 23.075,62.15 U1.144@24.325,62.15 ; v1(22.25,67.825) C53.2@22.25,68.55 C53.2@22.275,68.55 ; C53.2@22.25,68.525 C53.2@22.275,68.55 ; U1.131@24.275,68.75 23,68.75 22.8,68.55 C53.2@22.275,68.55 ; v1@26.012,85.512 25.325,84.825 25.325,84.1 25.43,83.995 25.455,83.995 26.275,83.175 26.275,82.925 ; v1(26.025,85.525) R64.1@26.775,85.525 ; 26.275,82.85 26.275,82.925 ; U1.108@26.3,81.825 26.282,81.843 26.282,82.918 26.275,82.925 ; C51.2@33.175,83.9 33.2,83.875 33.2,83.35 33.4,83.15 U1.94@33.4,81.875 ; C51.2@33.175,83.925 v1(33.175,84.575) ; C72.2@34.575,58.125 v1(35.2,58.125) ; v1(37.475,83.9) 38.2,83.9 C52.2@38.2,83.875 ; C52.2@38.175,83.9 C52.2@38.2,83.875 ; U1.84@38.4,81.875 38.4,83.15 38.2,83.35 C52.2@38.2,83.875 ; R68.1@45.95,56.25 v1(46.75,56.25) ; U1.52@45.975,69.75 47.25,69.75 47.45,69.95 C60.2@47.975,69.95 ; U1.62@45.975,74.75 47.25,74.75 47.45,74.95 C71.2@47.975,74.95 ; U1.72@45.975,79.85 47.35,79.85 47.446,79.946 47.996,79.946 C57.2@48,79.95 v1(48,80.675) ; C60.2@48,69.975 C60.2@47.975,69.95 ; v1(48,70.675) C60.2@48,69.95 C60.2@47.975,69.95 ; C71.2@48,74.975 C71.2@47.975,74.95 ; v1(48,75.675) C71.2@48,74.95 C71.2@47.975,74.95 ; v1(48.775,63.4) v1@48.823,63.448 ; JP5.2@51.755,106.05 51.755,103.97 51.95,103.775 R99.2@54.3,103.775
  other v1: 17.525,74.7 49.149,80.974 49.875,80.974 49.149,81.7 49.875,81.7
VDDA: C70.2 C77.2 R68.2 SB45.2 U1.33 | length 5.9
  Top Layer w0.25: U1.33@42.4,60.175 42.4,58.875 42.55,58.725 42.55,58.225 C77.2@42.5,58.175 ; C77.2@42.55,58.125 C70.2@42.55,57.25 42.55,56.3 42.6,56.25 SB45.2@42.65,56.25 R68.2@44.5,56.25
VDDIO2: C49.2 C50.2 C55.2 R62.2 U1.121 | length 6
  Top Layer w0.25: R62.2@18.5,73.3 C49.2@20,73.3 20.95,73.3 21.07,73.42 21.12,73.42 C55.2@21.25,73.55 C50.2@22.25,73.55 22.95,73.55 23.15,73.75 U1.121@24.325,73.75
VDDUSB: C59.2 R64.2 U1.106 | length 3.9
  Top Layer w0.25: U1.106@27.4,81.85 27.4,83.225 C59.2@28.175,84 ; C59.2@28.2,84.125 R64.2@28.2,85.525
VIN: CN6.8 CN7.24 R61.1 TP45.1
  other v1: 15.505,90.231 16.26,90.256 15.505,90.981 16.26,91.006
VREFP: C69.2 C76.2 SB10.1 SB45.1 U1.32 | length 52.4
  Top Layer w0.25: v1(40.975,56.25) SB45.1@41.675,56.25 41.7,56.276 C76.2@41.7,57.25 C69.2@41.7,58.125 41.7,58.675 41.9,58.875 U1.32@41.9,60.175 ; 52.65,87.019 v1(52.65,87.775)
  Signal Layer 2 w0.25: v1(40.975,56.25) 42.425,56.25 43.225,55.45 51.125,55.45 51.95,56.275 v1(53.175,56.275)
  Bottom Layer w0.25: 52.65,72.279 52.65,71.85 ; 52.65,85.175 52.65,84.425 ; v1(52.65,87.775) 52.65,84.425 ; v1(53.175,56.275) 53.175,64.099 51.88,65.394 51.88,71.08 52.65,71.85 ; 52.65,71.85 52.65,80.9 53.225,81.475 53.225,83.85 52.65,84.425
XSPI1.CLK: R108.1 SB26.1 U1.22 | length 68
  Top Layer w0.12: SB26.1@20.25,30.45 v1(21.375,30.45) ; v1(27.813,38.475) 30.072,38.475 31.373,39.775 31.373,40.061 32.841,41.53 32.841,41.786 33.855,42.8 33.855,43.321 34.229,43.695 37.1,43.695 37.475,43.32 R108.1@37.475,42.75 ; U1.22@36.9,60.175 v1(36.9,61.5)
  Signal Layer 2 w0.12: v1(21.375,30.45) 23.45,30.45 24.15,29.75 27.325,29.75 v1(27.813,29.262) ; v1(25,60.9) 25.54,60.36 35.76,60.36 v1(36.9,61.5)
  Bottom Layer w0.12: v1(25,60.9) 25.47,60.43 25.47,45.476 25.95,44.996 25.95,40.338 v1(27.813,38.475) v1(27.813,29.262) v1@27.825,29.25
XSPI1.DQS0: R107.1 SB28.1 U1.48 | length 75.9
  Top Layer w0.12: SB28.1@20.25,32.2 v1(21.375,32.2) ; v1(21.25,41.55) R107.1@30.25,41.55 ; v1(42.65,67.75) 44.825,67.75 U1.48@45.975,67.75
  Signal Layer 2 w0.12: v1(18.425,67.75) 19.385,68.71 40.772,68.71 41.732,67.75 v1(42.65,67.75)
  Bottom Layer w0.12: v1(18.425,67.75) 18.425,59.275 21.25,56.45 v1(21.25,41.55) 20.5,40.8 20.5,33.075 v1(21.375,32.2)
XSPI1.IO0: R51.1 SB7.1 U1.80 | length 88.9
  Top Layer w0.12: SB7.1@11,51.375 v1(12.25,51.375) ; U1.80@40.4,81.825 40.4,83.171 44.698,87.469 46.256,87.469 v1(47.025,86.7) ; R51.1@40.75,46.7 v1(40.75,47.375)
  Signal Layer 2 w0.12: v1(12.25,51.375) 12.975,50.65 16.075,50.65 16.45,50.275 29.263,50.275 30.188,49.35 38.775,49.35 v1(40.75,47.375)
  Bottom Layer w0.12: v1(40.75,47.375) 40.8,47.425 41.104,47.425 41.238,47.559 42.162,47.559 42.346,47.375 45.355,47.375 49.375,51.395 49.375,76.33 47.025,78.68 v1(47.025,86.7)
XSPI1.IO1: R52.1 SB15.1 U1.81 | length 87.6
  Top Layer w0.12: SB15.1@14.35,49.875 14.777,49.875 14.952,50.05 v1(15.6,50.05) ; R52.1@39.25,46.7 v1(39.25,47.375) ; U1.81@39.9,81.825 39.9,83.011 44.599,87.709 47.391,87.709 47.7,87.4 v1(47.725,87.4)
  Signal Layer 2 w0.12: v1(15.6,50.05) 15.615,50.035 29.164,50.035 30.089,49.11 37.515,49.11 v1(39.25,47.375)
  Bottom Layer w0.12: v1(39.25,47.375) 39.725,46.9 40.918,46.9 41.338,47.319 42.063,47.319 42.247,47.135 45.454,47.135 49.615,51.296 49.615,76.476 47.265,78.826 47.265,85.668 47.725,86.128 v1(47.725,87.4)
XSPI1.IO2: R53.1 SB16.1 U1.19 | length 68.4
  Top Layer w0.12: SB16.1@14.35,48.375 v1(15.6,48.375) ; U1.19@35.4,60.175 35.4,63.9 35.825,64.325 41.579,64.325 43.256,62.648 44.098,62.648 v1(44.45,63) ; R53.1@37.75,46.7 v1(37.75,47.375)
  Signal Layer 2 w0.12: v1(15.6,48.375) 20.2,48.375 21.62,49.795 29.065,49.795 29.99,48.87 37.13,48.87 37.75,48.25 v1(37.75,47.375) 37.75,46.625 38.225,46.15 40.271,46.15 41.245,47.124 41.245,47.841 42.809,49.405 46.555,49.405 v1(46.925,49.775)
  Bottom Layer w0.12: v1(44.45,63) 49.135,58.315 49.135,51.495 47.415,49.775 v1(46.925,49.775)
XSPI1.IO3: R56.1 SB17.1 U1.82 | length 98.3
  Top Layer w0.12: SB17.1@11,46 v1(12.25,46) ; R56.1@36.25,46.7 v1(36.25,47.375) ; U1.82@39.4,81.825 39.4,82.85 44.499,87.949 50.526,87.949 v1(51.15,87.325)
  Signal Layer 2 w0.12: v1(12.25,46) 13.411,46 14.565,47.155 19.33,47.155 21.73,49.555 28.965,49.555 29.89,48.63 34.995,48.63 v1(36.25,47.375) 37.725,45.9 40.361,45.9 41.485,47.024 41.485,47.741 42.909,49.165 48.665,49.165 v1(49.25,49.75)
  Bottom Layer w0.12: v1(49.25,49.75) 49.855,50.355 49.855,60.66 50.804,61.61 50.804,64.421 50.49,64.735 50.49,80.316 51.455,81.281 51.455,83.22 50.715,83.96 50.715,86.89 v1(51.15,87.325)
XSPI1.IO4: R57.1 SB18.1 U1.58 | length 74.7
  Top Layer w0.12: SB18.1@11,44.5 v1(12.25,44.5) ; R57.1@34.75,46.7 v1(34.75,47.375) ; U1.58@45.975,72.75 47.611,72.75 47.701,72.66 50.753,72.66 v1(51.575,71.838)
  Signal Layer 2 w0.12: v1(12.25,44.5) 14.665,46.915 19.44,46.915 21.84,49.315 28.866,49.315 29.791,48.39 34.182,48.39 34.75,47.822 v1(34.75,47.375) 36.475,45.65 40.45,45.65 41.725,46.925 41.725,47.642 43.008,48.925 v1(49.829,48.925)
  Bottom Layer w0.12: v1(49.829,48.925) 50.135,49.231 50.135,60.601 51.044,61.51 51.044,64.544 51.575,65.075 v1(51.575,71.838)
XSPI1.IO5: R58.1 SB20.1 U1.119 | length 65.5
  Top Layer w0.12: SB20.1@11,43 v1(12.25,43) ; U1.119@24.325,74.75 v1(31.325,74.75) ; R58.1@33.25,46.7 v1(33.25,47.375)
  Signal Layer 2 w0.12: v1(12.25,43) 13.025,43.775 13.025,44.936 14.764,46.675 19.539,46.675 21.939,49.075 28.766,49.075 29.691,48.15 32.475,48.15 v1(33.25,47.375)
  Bottom Layer w0.12: v1(31.325,74.75) 30.681,74.106 30.681,70.688 30.925,70.445 30.925,67.15 29.94,66.165 29.94,63.994 28.465,62.519 28.465,58.049 29.655,56.859 29.655,53.745 30.625,52.775 30.625,52.05 30.035,51.46 30.035,49.785 31.57,48.25 32.375,48.25 v1(33.25,47.375)
XSPI1.IO6: R63.1 SB21.1 U1.122 | length 59.4
  Top Layer w0.12: SB21.1@11,41.5 v1(12.25,41.5) ; U1.122@24.325,73.25 24.415,73.34 25.145,73.34 25.93,74.125 27.175,74.125 v1(27.975,73.325) ; R63.1@31.75,46.7 v1(31.75,47.375)
  Signal Layer 2 w0.12: v1(12.25,41.5) 13.265,42.515 13.265,44.836 14.864,46.435 19.639,46.435 22.039,48.835 28.667,48.835 29.592,47.91 31.215,47.91 v1(31.75,47.375)
  Bottom Layer w0.12: v1(27.975,73.325) 27.975,71.918 28.235,71.658 28.235,70.349 27.66,69.774 27.66,63.05 26.945,62.335 26.945,59.23 29.415,56.76 29.415,52.324 29.795,51.944 29.795,51.487 29.795,49.33 v1(31.75,47.375)
XSPI1.IO7: R66.1 SB22.1 U1.26 | length 57.9
  Top Layer w0.12: SB22.1@11,40 v1(12.25,40) ; R66.1@30.25,46.7 v1(30.25,47.375) ; U1.26@38.9,60.175 v1(38.9,62.85)
  Signal Layer 2 w0.12: v1(12.25,40) 13.505,41.255 13.505,44.737 14.963,46.195 19.738,46.195 22.138,48.595 28.567,48.595 29.787,47.375 v1(30.25,47.375) ; v1(26.7,62.85) v1(38.9,62.85)
  Bottom Layer w0.12: v1(26.7,62.85) 26.705,62.845 26.705,59.131 29.175,56.661 29.175,52.225 29.555,51.845 29.555,51.587 29.555,48.07 v1(30.25,47.375)
XSPI1.NCLK: R109.1 SB27.1 U1.135 | length 63.5
  Top Layer w0.12: SB27.1@20.25,28.7 v1(21.375,28.7) ; U1.135@24.325,66.75 v1(25.9,66.75) ; v1(26.43,39.095) 30.353,39.095 31.12,39.862 31.12,40.148 32.49,41.518 32.49,42.882 33.543,43.935 38.332,43.935 38.825,43.442 R109.1@38.825,42.75
  Signal Layer 2 w0.12: v1(21.375,28.7) 26.35,28.7 v1(26.425,28.625)
  Bottom Layer w0.12: v1(25.9,66.75) 24.545,65.395 24.545,58.305 25.23,57.62 25.23,45.377 25.71,44.897 25.71,39.815 v1(26.43,39.095) 26.43,28.63 v1(26.425,28.625)
XSPI1.NCS1: R67.1 SB23.1 U1.69 | length 74.4
  Top Layer w0.12: SB23.1@20.25,35.7 v1(21.375,35.7) ; v1(24.6,46.45) 26.9,48.75 R67.1@29.55,48.75 ; v1(44.325,78.475) 44.55,78.25 U1.69@45.975,78.25
  Signal Layer 2 w0.12: v1(21.375,35.7) 22.2,34.875 v1(24.65,34.875) ; v1(27.75,78.475) v1(44.325,78.475)
  Bottom Layer w0.12: v1(24.65,34.875) 24.95,35.175 24.95,46.1 v1(24.6,46.45) 24.6,57.911 24.305,58.206 24.305,73.105 27.75,76.55 v1(27.75,78.475)
XSPI1.NCS2: R106.1 SB24.1 U1.114 | length 58.8
  Top Layer w0.12: SB24.1@20.25,33.95 v1(21.375,33.95) ; v1(23.875,46.85) 24.357,46.85 26.607,49.1 27.8,49.1 28.95,50.25 R106.1@29.55,50.25 ; U1.114@24.325,77.25 26.55,77.25 v1(27.175,76.625)
  Signal Layer 2 w0.12: v1(21.375,33.95) v1(23.875,33.95)
  Bottom Layer w0.12: v1(23.875,33.95) 23.875,34.85 24.71,35.685 24.71,45.403 23.875,46.238 v1(23.875,46.85) 23.875,47.386 24.36,47.871 24.36,57.811 24.065,58.106 24.065,73.515 v1(27.175,76.625)
pads on no net: CN1.0 CN1.A2 CN1.A3 CN1.A8 CN1.A10 CN1.A11 CN1.B2 CN1.B3 CN1.B8 CN1.B10 CN1.B11 CN4.7 CN10.12 CN10.14 CN11.2 CN11.4 CN11.6 CN11.8 CN11.10 CN11.12 CN11.14 CN11.16 CN11.18 CN11.20 CN11.22 CN11.24 CN11.26 CN11.27 CN11.28 CN11.29 CN11.30 CN11.31 CN11.32 CN12.9 CN12.10 CN12.17 CN12.19 CN12.20 CN12.21 CN12.22 CN12.23 CN12.24 CN12.25 CN12.26 CN12.27 CN12.28 CN12.29 CN12.30 CN12.31 CN12.32 CN13.0 CN13.A2 CN13.A3 CN13.A8 CN13.A10 CN13.A11 CN13.B2 CN13.B3 CN13.B8 CN13.B10 CN13.B11 CN19.0 CN19.3 CN19.5 CN19.6 CN19.46 CN19.48 CN19.52 CN19.68 HW10.1 HW11.1 HW12.1 HW13.1 U1.0 U2.A1 U2.A2 U2.A3 U2.A4 U2.A5 U2.A8 U2.A9 U2.A11 U2.A12 U2.A13 U2.B1 U2.B2 U2.B3 U2.B4 U2.B5 U2.B6 U2.B7 U2.B8 U2.B9 U2.B10 U2.B11 U2.B12 U2.B13 U2.B14 U2.B15 U2.C2 U2.C3 U2.C12 U2.C13 U2.C14 U2.C15 U2.D1 U2.D2 U2.D3 U2.D11 U2.D13 U2.D14 U2.E1 U2.E2 U2.E3 U2.E4 U2.E12 U2.E13 U2.E14 U2.E15 U2.F1 U2.F4 U2.F14 U2.G4 U2.G14 U2.G15 U2.H2 U2.H3 U2.H4 U2.H14 U2.J3 U2.J4 U2.K1 U2.K2 U2.K3 U2.K12 U2.K13 U2.K14 U2.K15 U2.L1 U2.L12 U2.L13 U2.L14 U2.L15 U2.M2 U2.M3 U2.M4 U2.M7 U2.M12 U2.M13 U2.M14 U2.M15 U2.N2 U2.N4 U2.N6 U2.N7 U2.N11 U2.N13 U2.N14 U2.N15 U2.P2 U2.P4 U2.P5 U2.P6 U2.P7 U2.P8 U2.P9 U2.P10 U2.P11 U2.P12 U2.P13 U2.P14 U2.P15 U2.R2 U2.R3 U2.R6 U2.R7 U2.R8 U2.R9 U2.R10 U2.R11 U2.R12 U2.R13 U7.3 U7.4 U7.6 U11.4 U16.5 U19.4 U19.5 U19.12 U19.13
